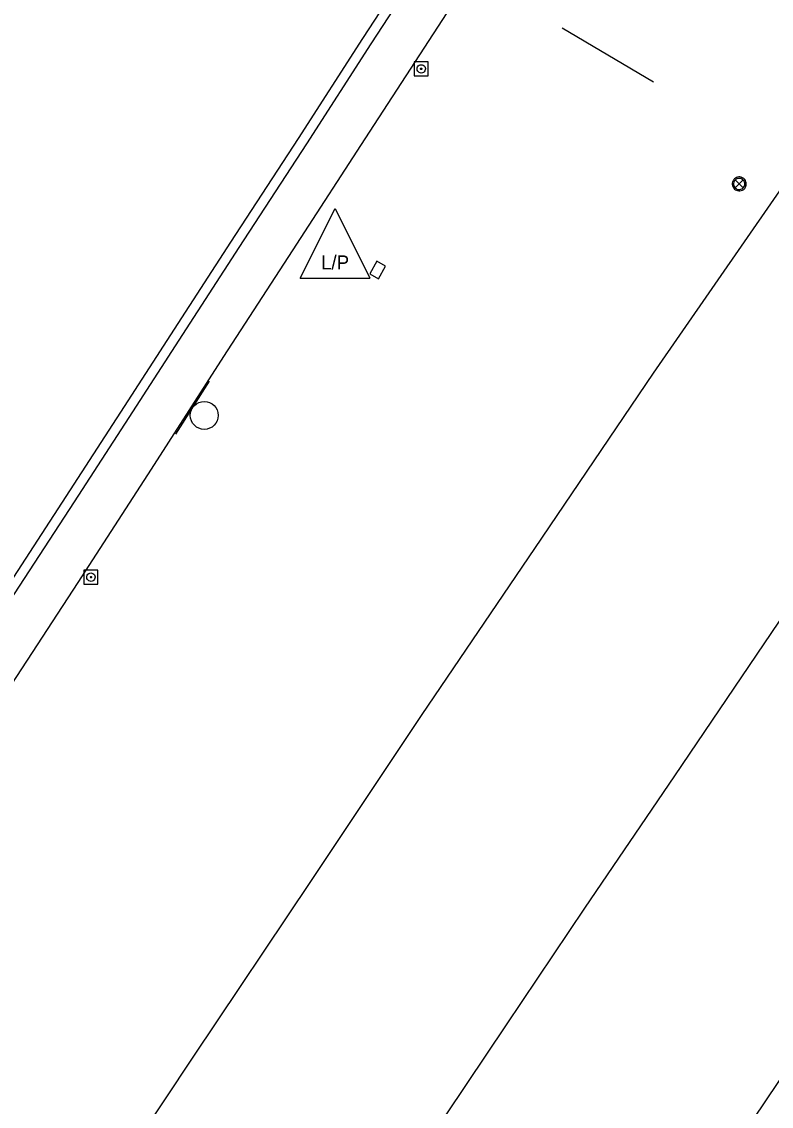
# Model space of a CAD drawing. Extents: x 2161152 to 2175754, y 602179 to 617749.
# Drawn here: x 2162297.9 to 2162405.3, y 604333.2 to 604488.6 of the extents above; entities that cross this region are included whole.
import ezdxf

# ---------------------------------------------------------------- set-up
doc = ezdxf.new("R2010")
doc.units = 0
for name, color, linetype in [('RD_EX_BldgApp_Post', 7, 'Continuous'), ('RD_EX_BldgApp_Sign', 7, 'Continuous'), ('RD_EX_Conc_Curb', 7, 'Continuous'), ('RD_EX_Conc_Gutter', 7, 'Continuous'), ('RD_EX_Conc_Sidewalk', 7, 'Continuous'), ('RD_EX_Fence_Other', 7, 'Continuous'), ('RD_EX_Misc', 7, 'Continuous'), ('RD_EX_Road', 7, 'Continuous'), ('RD_EX_UT', 7, 'Continuous')]:
    doc.layers.add(name, color=color, linetype=linetype)

msp = doc.modelspace()

# ---------------------------------------------------------------- linework, layer by layer
at = {"layer": 'RD_EX_BldgApp_Post'}
for p, q in [((2162401.29, 604464.8), (2162400.15, 604465.93)), ((2162400.15, 604464.8), (2162401.29, 604465.93))]:
    msp.add_line(p, q, dxfattribs=at)
for points in [[(2162401.72, 604465.36), (2162401.71, 604465.52), (2162401.67, 604465.68), (2162401.6, 604465.85), (2162401.5, 604466), (2162401.36, 604466.14), (2162401.19, 604466.25), (2162401.01, 604466.32), (2162400.82, 604466.36), (2162400.64, 604466.36), (2162400.47, 604466.33), (2162400.31, 604466.28), (2162400.18, 604466.21), (2162400.05, 604466.11), (2162399.93, 604465.98), (2162399.84, 604465.83), (2162399.76, 604465.66), (2162399.72, 604465.46), (2162399.72, 604465.27), (2162399.76, 604465.07), (2162399.84, 604464.9), (2162399.93, 604464.74), (2162400.05, 604464.62), (2162400.18, 604464.52), (2162400.31, 604464.45), (2162400.47, 604464.4), (2162400.64, 604464.37), (2162400.82, 604464.37), (2162401.01, 604464.4), (2162401.19, 604464.48), (2162401.36, 604464.59), (2162401.5, 604464.73), (2162401.6, 604464.88), (2162401.67, 604465.05), (2162401.71, 604465.21), (2162401.72, 604465.36)], [(2162401.52, 604465.36), (2162401.51, 604465.49), (2162401.48, 604465.62), (2162401.43, 604465.75), (2162401.34, 604465.87), (2162401.23, 604465.98), (2162401.1, 604466.07), (2162400.95, 604466.13), (2162400.8, 604466.16), (2162400.65, 604466.16), (2162400.52, 604466.14), (2162400.39, 604466.1), (2162400.29, 604466.04), (2162400.19, 604465.96), (2162400.09, 604465.86), (2162400.01, 604465.74), (2162399.95, 604465.6), (2162399.92, 604465.44), (2162399.92, 604465.29), (2162399.95, 604465.13), (2162400.01, 604464.99), (2162400.09, 604464.87), (2162400.19, 604464.77), (2162400.29, 604464.69), (2162400.39, 604464.63), (2162400.52, 604464.59), (2162400.65, 604464.57), (2162400.8, 604464.57), (2162400.95, 604464.6), (2162401.1, 604464.66), (2162401.23, 604464.74), (2162401.34, 604464.86), (2162401.43, 604464.98), (2162401.48, 604465.11), (2162401.51, 604465.24), (2162401.52, 604465.36)]]:
    msp.add_lwpolyline(points, dxfattribs=at)
at = {"layer": 'RD_EX_BldgApp_Sign'}
for p, q in [((2162375.36, 604487.74), (2162388.44, 604480)), ((2162324.76, 604437.09), (2162319.91, 604429.5))]:
    msp.add_line(p, q, dxfattribs=at)
msp.add_circle((2162324.03, 604432.19), 2, dxfattribs=at)
at = {"layer": 'RD_EX_Conc_Curb'}
msp.add_lwpolyline([(2162248.4, 604331.76), (2162254.92, 604341.51), (2162262.84, 604353.79), (2162269.69, 604364.57), (2162279.08, 604379.14), (2162287.34, 604391.86), (2162296.14, 604405.51), (2162305.41, 604419.79), (2162313.25, 604431.9), (2162320.96, 604443.81), (2162329.03, 604456.25), (2162338.72, 604471.11), (2162347.94, 604485.43), (2162355.44, 604496.96)], dxfattribs=at)
at = {"layer": 'RD_EX_Conc_Gutter'}
msp.add_lwpolyline([(2162247.22, 604332.53), (2162253.74, 604342.28), (2162261.65, 604354.55), (2162268.5, 604365.33), (2162277.89, 604379.91), (2162286.16, 604392.63), (2162294.95, 604406.28), (2162304.23, 604420.56), (2162312.07, 604432.67), (2162319.78, 604444.57), (2162327.85, 604457.02), (2162337.54, 604471.87), (2162346.76, 604486.2), (2162354.26, 604497.73)], dxfattribs=at)
at = {"layer": 'RD_EX_Conc_Sidewalk'}
msp.add_lwpolyline([(2162255.05, 604329.62), (2162260.91, 604338.54), (2162269.61, 604352), (2162277.47, 604364.24), (2162287.92, 604380.57), (2162296.44, 604393.67), (2162305.94, 604408.26), (2162316.47, 604424.49), (2162326.82, 604440.64), (2162337.29, 604456.71), (2162347.12, 604471.83), (2162360.79, 604492.95), (2162374.63, 604514.3), (2162387.54, 604534.07), (2162401.1, 604555.26), (2162398.75, 604556.99), (2162396.1, 604558.59)], dxfattribs=at)
at = {"layer": 'RD_EX_Fence_Other'}
msp.add_lwpolyline([(2162232.38, 604067.21), (2162284.43, 604150.47), (2162337.26, 604232.38), (2162363.46, 604272.19), (2162397.57, 604323.62), (2162428.9, 604370.18), (2162461.59, 604418.14), (2162486.44, 604453.93), (2162511.5, 604489.58), (2162532.17, 604518.67), (2162568.74, 604569.4), (2162595.2, 604606.09), (2162621.99, 604642.55), (2162649.09, 604678.78), (2162654.18, 604685.5), (2162696.93, 604742.36), (2162714.01, 604764.54), (2162730.82, 604786.76), (2162752.93, 604817.73)], dxfattribs=at)
at = {"layer": 'RD_EX_Misc'}
for points in [[(2162354.13, 604480.85), (2162356.13, 604480.85), (2162356.13, 604482.85), (2162354.13, 604482.85), (2162354.13, 604480.85)], [(2162354.53, 604481.85), (2162354.55, 604482.01), (2162354.61, 604482.15), (2162354.7, 604482.27), (2162354.82, 604482.37), (2162354.96, 604482.43), (2162355.12, 604482.45), (2162355.27, 604482.44), (2162355.41, 604482.39), (2162355.54, 604482.3), (2162355.64, 604482.18), (2162355.7, 604482.04), (2162355.73, 604481.89), (2162355.73, 604481.85)], [(2162355.73, 604481.85), (2162355.71, 604481.7), (2162355.66, 604481.56), (2162355.57, 604481.44), (2162355.45, 604481.34), (2162355.31, 604481.28), (2162355.15, 604481.25), (2162355, 604481.27), (2162354.86, 604481.32), (2162354.73, 604481.41), (2162354.63, 604481.53), (2162354.56, 604481.67), (2162354.54, 604481.82), (2162354.53, 604481.85)], [(2162355.03, 604481.85), (2162355.05, 604481.91), (2162355.1, 604481.95), (2162355.17, 604481.95), (2162355.22, 604481.91), (2162355.23, 604481.85)], [(2162355.23, 604481.85), (2162355.22, 604481.8), (2162355.17, 604481.76), (2162355.1, 604481.76), (2162355.05, 604481.8), (2162355.03, 604481.85)], [(2162306.79, 604408.01), (2162308.79, 604408.01), (2162308.79, 604410.01), (2162306.79, 604410.01), (2162306.79, 604408.01)], [(2162307.19, 604409.01), (2162307.21, 604409.17), (2162307.27, 604409.31), (2162307.36, 604409.43), (2162307.48, 604409.53), (2162307.62, 604409.59), (2162307.77, 604409.61), (2162307.93, 604409.6), (2162308.07, 604409.55), (2162308.2, 604409.46), (2162308.29, 604409.34), (2162308.36, 604409.2), (2162308.39, 604409.05), (2162308.39, 604409.01)], [(2162308.39, 604409.01), (2162308.37, 604408.86), (2162308.31, 604408.72), (2162308.22, 604408.6), (2162308.1, 604408.5), (2162307.96, 604408.44), (2162307.81, 604408.41), (2162307.66, 604408.43), (2162307.51, 604408.48), (2162307.39, 604408.57), (2162307.29, 604408.69), (2162307.22, 604408.82), (2162307.19, 604408.98), (2162307.19, 604409.01)], [(2162307.69, 604409.01), (2162307.71, 604409.07), (2162307.76, 604409.11), (2162307.82, 604409.11), (2162307.87, 604409.07), (2162307.89, 604409.01)], [(2162307.89, 604409.01), (2162307.87, 604408.95), (2162307.82, 604408.92), (2162307.76, 604408.92), (2162307.71, 604408.95), (2162307.69, 604409.01)]]:
    msp.add_lwpolyline(points, dxfattribs=at)
at = {"layer": 'RD_EX_Road'}
for points in [[(2162493.91, 604588.8), (2162484.11, 604575.21), (2162469.71, 604554.81), (2162458.68, 604539.44), (2162448.06, 604524.32), (2162432.06, 604501.34), (2162420.29, 604484.34), (2162405.62, 604463.12), (2162388.38, 604438.25), (2162371.36, 604413.12), (2162355.23, 604389.34), (2162339.24, 604365.42), (2162322.49, 604340.38), (2162305.12, 604314.19)], [(2162355.89, 604327.74), (2162367.34, 604344.88), (2162378.6, 604361.56), (2162391.48, 604380.55), (2162407.5, 604404.18), (2162417.87, 604419.28), (2162428.32, 604434.31), (2162439.37, 604450.42), (2162450.2, 604466.3), (2162459.62, 604479.71), (2162471.57, 604496.89), (2162482.95, 604513.11), (2162494.96, 604530.15), (2162507.61, 604547.97), (2162521.64, 604567.61), (2162535.9, 604587.44)]]:
    msp.add_lwpolyline(points, dxfattribs=at)
at = {"layer": 'RD_EX_UT'}
for p, q in [((2162337.79, 604451.84), (2162342.79, 604461.84)), ((2162342.79, 604461.84), (2162347.79, 604451.84)), ((2162337.79, 604451.84), (2162347.79, 604451.84))]:
    msp.add_line(p, q, dxfattribs=at)
msp.add_lwpolyline([(2162347.75, 604452.49), (2162349, 604451.78), (2162350.03, 604453.6), (2162348.78, 604454.31), (2162347.75, 604452.49)], dxfattribs=at)

# ---------------------------------------------------------------- texts
msp.add_text('L/P', height=2, dxfattribs=at).set_placement((2162340.78, 604453.12))

doc.saveas('drawing.dxf')
